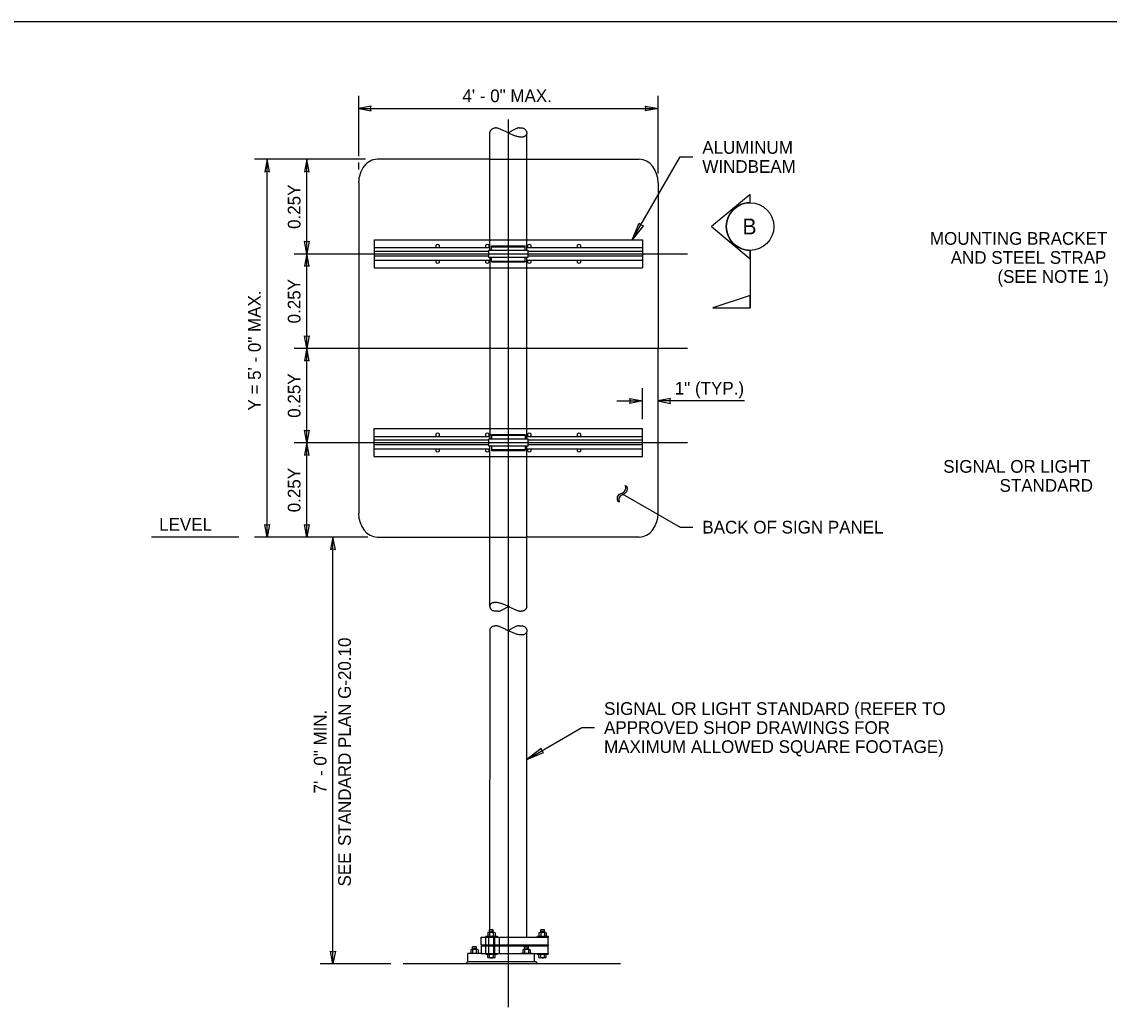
# Model space of a CAD drawing. Extents: x 99862 to 104211, y 98939 to 105076.
# Drawn here: x 101066 to 102436, y 103829 to 105076 of the extents above; entities that cross this region are included whole.
import ezdxf

# ---------------------------------------------------------------- set-up
doc = ezdxf.new("R2010")
doc.units = 0
for name, color, linetype in [('Level 1', 7, 'Continuous'), ('Level 15', 7, 'Continuous'), ('Level 18', 7, 'Continuous'), ('Level 19', 7, 'Continuous'), ('Level 2', 7, 'Continuous'), ('Level 20', 7, 'Continuous'), ('Level 3', 7, 'Continuous'), ('Level 6', 7, 'Continuous'), ('Level 7', 7, 'Continuous')]:
    doc.layers.add(name, color=color, linetype=linetype)

msp = doc.modelspace()

# ---------------------------------------------------------------- linework, layer by layer
at = {"layer": 'Level 1'}
for p, q in [((101656.2, 104902.1), (101514.3, 104902.1)), ((101656.2, 104902.1), (101702.5, 104902.1)), ((101702.5, 104902.1), (101844.4, 104902.1)), ((101490.8, 104872.3), (101490.8, 104455.6)), ((101868, 104872.3), (101867.9, 104455.6)), ((101868, 104872.3), (101868, 104872.3)), ((101867.9, 104455.6), (101867.9, 104455.6)), ((101514.3, 104425.8), (101656.2, 104425.8)), ((101656.2, 104425.8), (101702.5, 104425.8)), ((101844.4, 104425.8), (101702.5, 104425.8)), ((101844.4, 104425.8), (101844.4, 104425.8))]:
    msp.add_line(p, q, dxfattribs=at)
msp.add_lwpolyline([(99862, 102999.5), (103151, 102999.5), (103151, 105075.5), (99862, 105075.5)], close=True, dxfattribs=at)
for centre, major_axis, start_param, end_param in [((101514.3, 104872.3), (0, 29.8), 6.28312, 7.853976), ((101844.4, 104872.3), (0, -29.8), 1.570785, 3.141503), ((101514.3, 104455.6), (0, -29.8), 4.712329, 6.283073), ((101844.4, 104455.6), (0, -29.8), 0, 1.570789)]:
    msp.add_ellipse(centre, major_axis=major_axis, ratio=0.792, start_param=start_param, end_param=end_param, dxfattribs=at)
at = {"layer": 'Level 15'}
for p, q in [((101490.8, 104906.1), (101490.8, 104982.1)), ((101868, 104884.3), (101868, 104982.1)), ((101490.8, 104966.1), (101868, 104966.1)), ((101679.4, 103833.2), (101679.4, 104952.4)), ((101499.3, 104902.1), (101359.5, 104902.1)), ((101375.5, 104425.8), (101375.5, 104902.1)), ((101425.5, 104783), (101425.5, 104902.1)), ((101835.5, 104800.5), (101895.8, 104905)), ((101895.8, 104905), (101911.8, 104905)), ((101490.8, 104889.1), (101490.8, 104898.1)), ((101409.5, 104783), (101905.3, 104783)), ((101425.5, 104663.9), (101425.5, 104783)), ((101409.5, 104663.9), (101905.3, 104664)), ((101425.5, 104544.9), (101425.5, 104663.9)), ((101848.2, 104574.6), (101848.2, 104613.5)), ((101816.2, 104597.5), (101848.2, 104597.5)), ((101977.1, 104597.5), (101867.9, 104597.5)), ((101409.5, 104544.9), (101905.3, 104544.9)), ((101425.5, 104425.8), (101425.5, 104544.9)), ((101827.2, 104488.6), (101826.6, 104491)), ((101826.6, 104491), (101828.3, 104489.8)), ((101828.3, 104489.8), (101829, 104487.9)), ((101816.7, 104474.8), (101817, 104476.4)), ((101817, 104476.4), (101817.7, 104477.9)), ((101817.7, 104477.9), (101819.4, 104479.7)), ((101819.3, 104476.3), (101818.7, 104475)), ((101820.3, 104477.4), (101819.3, 104476.3)), ((101819.4, 104479.7), (101823, 104481.7)), ((101822.4, 104478.7), (101820.3, 104477.4)), ((101826.2, 104480.9), (101822.4, 104478.7)), ((101822.9, 104480.3), (101895.8, 104438.2)), ((101823, 104481.7), (101825.1, 104483)), ((101825.1, 104483), (101826.5, 104484.4)), ((101828.1, 104482.9), (101826.2, 104480.9)), ((101826.5, 104484.4), (101827.1, 104485.6)), ((101827.1, 104485.6), (101827.3, 104486.9)), ((101827.3, 104486.9), (101827.2, 104488.6)), ((101828.8, 104484.5), (101828.1, 104482.9)), ((101829.2, 104486.2), (101828.8, 104484.5)), ((101829, 104487.9), (101829.2, 104486.2)), ((101816.8, 104473), (101816.7, 104474.8)), ((101817.5, 104470.9), (101816.8, 104473)), ((101819.2, 104469.8), (101817.5, 104470.9)), ((101818.7, 104475), (101818.5, 104473.4)), ((101818.5, 104473.4), (101819.2, 104469.8)), ((101895.8, 104438.2), (101911.8, 104438.2)), ((101339.7, 104425.8), (101229.7, 104425.8)), ((101502.3, 104425.8), (101359.5, 104425.8)), ((101458.3, 103887.9), (101458.3, 104425.8)), ((101702.5, 104145.4), (101772, 104185.6)), ((101772, 104185.6), (101788, 104185.6)), ((101531.4, 103887.9), (101442.3, 103887.9))]:
    msp.add_line(p, q, dxfattribs=at)
for points in [[(101490.8, 104966.1), (101506.5, 104963), (101505.8, 104966.1), (101506.5, 104969.2)], [(101868, 104966.1), (101852.2, 104963), (101853, 104966.1), (101852.2, 104969.2)], [(101375.5, 104902.1), (101372.4, 104886.4), (101375.5, 104887.1), (101378.6, 104886.4)], [(101425.5, 104902.1), (101422.4, 104886.3), (101425.5, 104887.1), (101428.6, 104886.3)], [(101835.5, 104800.5), (101844.3, 104821.7), (101846.4, 104819.3), (101849.5, 104818.8)], [(101425.5, 104783), (101422.4, 104798.7), (101425.5, 104798), (101428.6, 104798.7)], [(101425.5, 104783), (101422.4, 104767.3), (101425.5, 104768), (101428.6, 104767.3)], [(101425.5, 104663.9), (101422.4, 104679.7), (101425.5, 104678.9), (101428.6, 104679.7)], [(101425.5, 104663.9), (101422.4, 104648.2), (101425.5, 104648.9), (101428.6, 104648.2)], [(101848.2, 104597.5), (101832.4, 104594.4), (101833.2, 104597.5), (101832.4, 104600.6)], [(101867.9, 104597.5), (101883.7, 104594.4), (101882.9, 104597.5), (101883.7, 104600.6)], [(101425.5, 104544.9), (101422.4, 104560.6), (101425.5, 104559.9), (101428.6, 104560.6)], [(101425.5, 104544.9), (101422.4, 104529.2), (101425.5, 104529.9), (101428.6, 104529.2)], [(101375.5, 104425.8), (101372.4, 104441.6), (101375.5, 104440.8), (101378.6, 104441.6)], [(101425.5, 104425.8), (101422.4, 104441.6), (101425.5, 104440.8), (101428.6, 104441.6)], [(101458.3, 104425.8), (101455.2, 104410.1), (101458.3, 104410.8), (101461.4, 104410.1)], [(101702.5, 104145.4), (101723.8, 104154.3), (101721.4, 104156.3), (101720.8, 104159.4)], [(101458.3, 103887.9), (101455.2, 103903.6), (101458.3, 103902.9), (101461.4, 103903.6)]]:
    msp.add_lwpolyline(points, close=True, dxfattribs=at)
at = {"layer": 'Level 18'}
for p, q in [((101661.5, 103927.2), (101654.5, 103927.2)), ((101655.5, 103927.2), (101655.5, 103930.5)), ((101660.4, 103930.5), (101655.5, 103930.5)), ((101656.8, 103928.9), (101659.3, 103928.9)), ((101660.4, 103927.2), (101660.4, 103930.5)), ((101726.1, 103927.2), (101719.1, 103927.2)), ((101720.1, 103927.2), (101720.1, 103930.5)), ((101725, 103930.5), (101720.1, 103930.5)), ((101721.3, 103928.9), (101723.9, 103928.9)), ((101725, 103927.2), (101725, 103930.5)), ((101645, 103911.7), (101645, 103921.5)), ((101645, 103921.5), (101729.5, 103921.5)), ((101651.1, 103922.7), (101665.1, 103922.7)), ((101651.1, 103922.7), (101651.1, 103921.5)), ((101651.1, 103911.7), (101651.1, 103921.5)), ((101653.4, 103926.8), (101653.4, 103922.7)), ((101654.8, 103911.7), (101654.8, 103921.5)), ((101655.6, 103926.9), (101655.6, 103922.7)), ((101660.3, 103926.9), (101660.3, 103922.7)), ((101661, 103911.7), (101661, 103921.5)), ((101662.2, 103911.7), (101662.2, 103921.5)), ((101662.6, 103926.8), (101662.6, 103922.7)), ((101665.1, 103922.7), (101665.1, 103921.5)), ((101668.4, 103911.7), (101668.4, 103921.5)), ((101715.5, 103922.7), (101729.5, 103922.7)), ((101715.5, 103922.7), (101715.5, 103921.5)), ((101717.9, 103926.8), (101717.9, 103922.7)), ((101720.2, 103926.9), (101720.2, 103922.7)), ((101724.9, 103926.9), (101724.9, 103922.7)), ((101727.2, 103926.8), (101727.2, 103922.7)), ((101729.5, 103922.7), (101729.5, 103921.5)), ((101729.5, 103911.7), (101729.5, 103921.5)), ((101628.2, 103890.7), (101628.2, 103900.6)), ((101645, 103900.6), (101628.2, 103900.6)), ((101629.4, 103901.4), (101643.7, 103901.4)), ((101629.4, 103901.4), (101629.4, 103900.6)), ((101632, 103905.5), (101632, 103901.4)), ((101640.1, 103905.9), (101633.2, 103905.9)), ((101634.2, 103905.9), (101634.2, 103909.2)), ((101639.1, 103909.2), (101634.2, 103909.2)), ((101634.3, 103905.5), (101634.3, 103901.4)), ((101635.4, 103907.6), (101638, 103907.6)), ((101639, 103905.6), (101639, 103901.4)), ((101639.1, 103905.9), (101639.1, 103909.2)), ((101641.3, 103905.5), (101641.3, 103901.4)), ((101643.7, 103901.4), (101643.7, 103900.6)), ((101645, 103911.7), (101729.5, 103911.7)), ((101645, 103910.4), (101729.5, 103910.4)), ((101645, 103910.4), (101645, 103900.6)), ((101645, 103900.6), (101729.5, 103900.6)), ((101651.1, 103911.7), (101651.1, 103910.4)), ((101651.1, 103900.6), (101651.1, 103910.4)), ((101651.1, 103900.6), (101651.1, 103899.8)), ((101651.1, 103899.8), (101665.1, 103899.8)), ((101653.6, 103895.7), (101653.6, 103899.8)), ((101654.8, 103900.6), (101654.8, 103910.4)), ((101655.8, 103895.6), (101655.8, 103899.8)), ((101660.5, 103895.6), (101660.5, 103899.8)), ((101661, 103900.6), (101661, 103910.4)), ((101662.2, 103900.6), (101662.2, 103910.4)), ((101662.8, 103895.7), (101662.8, 103899.8)), ((101665.1, 103911.7), (101665.1, 103910.4)), ((101665.1, 103900.6), (101665.1, 103899.8)), ((101668.4, 103900.6), (101668.4, 103910.4)), ((101695, 103901.4), (101709.4, 103901.4)), ((101695, 103901.4), (101695, 103900.6)), ((101697.6, 103905.5), (101697.6, 103901.4)), ((101705.8, 103905.9), (101698.8, 103905.9)), ((101699.8, 103905.9), (101699.8, 103909.2)), ((101704.7, 103909.2), (101699.8, 103909.2)), ((101699.9, 103905.5), (101699.9, 103901.4)), ((101701, 103907.6), (101703.6, 103907.6)), ((101704.6, 103905.6), (101704.6, 103901.4)), ((101704.7, 103905.9), (101704.7, 103909.2)), ((101706.9, 103905.5), (101706.9, 103901.4)), ((101709.4, 103901.4), (101709.4, 103900.6)), ((101712.2, 103890.7), (101712.2, 103900.6)), ((101715.5, 103911.7), (101715.5, 103910.4)), ((101715.5, 103900.6), (101715.5, 103899.8)), ((101715.5, 103899.8), (101729.5, 103899.8)), ((101717.9, 103895.7), (101717.9, 103899.8)), ((101720.2, 103895.6), (101720.2, 103899.8)), ((101724.9, 103895.6), (101724.9, 103899.8)), ((101727.2, 103895.7), (101727.2, 103899.8)), ((101729.5, 103911.7), (101729.5, 103910.4)), ((101729.5, 103900.6), (101729.5, 103910.4)), ((101729.5, 103900.6), (101729.5, 103899.8)), ((101820.7, 103887.9), (101546.9, 103887.9)), ((101625.3, 103887.9), (101628.2, 103890.7)), ((101628.2, 103890.7), (101713.9, 103890.7)), ((101661.7, 103895.3), (101654.7, 103895.3)), ((101716.7, 103887.9), (101713.9, 103890.7)), ((101726.1, 103895.3), (101719.1, 103895.3))]:
    msp.add_line(p, q, dxfattribs=at)
for centre, radius, start, end in [((101654.5, 103925.4), 1.81, 52.3034, 130.9523), ((101658, 103919.5), 7.78, 72.912, 107.9146), ((101661.4, 103925.3), 1.95, 52.6587, 124.5047), ((101719.1, 103925.4), 1.81, 52.3034, 130.9523), ((101722.6, 103919.5), 7.78, 72.912, 107.9146), ((101726, 103925.3), 1.95, 52.6587, 124.5047), ((101633.2, 103904.1), 1.81, 52.3034, 130.9523), ((101636.7, 103898.1), 7.78, 72.912, 107.9146), ((101640.1, 103904), 1.95, 52.6587, 124.5047), ((101698.8, 103904.1), 1.81, 52.3034, 130.9523), ((101702.3, 103898.1), 7.78, 72.912, 107.9146), ((101705.7, 103904), 1.95, 52.6587, 124.5047), ((101654.7, 103897.1), 1.81, 229.0477, 307.6966), ((101658.2, 103903), 7.78, 252.0854, 287.088), ((101661.6, 103897.2), 1.95, 235.4953, 307.3413), ((101719.1, 103897.1), 1.81, 229.0477, 307.6966), ((101722.6, 103903), 7.78, 252.0854, 287.088), ((101726, 103897.2), 1.95, 235.4953, 307.3413)]:
    msp.add_arc(centre, radius, start, end, dxfattribs=at)
at = {"layer": 'Level 19'}
for p, q in [((101656.2, 104787.6), (101656.2, 104935.8)), ((101702.5, 104787.6), (101702.5, 104934.3)), ((101656.2, 104778.2), (101656.2, 104549.7)), ((101702.5, 104549.7), (101702.5, 104778.2)), ((101656.2, 104338.7), (101656.2, 104540.3)), ((101702.5, 104338.4), (101702.5, 104540.3)), ((101656.1, 103930.5), (101656.3, 104309.7)), ((101702.5, 103921.5), (101702.5, 104306.4))]:
    msp.add_line(p, q, dxfattribs=at)
for points in [[(101692.8, 104941.6), (101695.8, 104941.6)], [(101666, 104332.2), (101663.1, 104332.2)], [(101692.8, 104314), (101695.8, 104314)]]:
    msp.add_lwpolyline(points, dxfattribs=at)
for points in [[(101656.2, 104935.3), (101656.2, 104935.4), (101656.2, 104935.9), (101656.3, 104936.6), (101656.6, 104937.5), (101657.1, 104938.5), (101657.8, 104939.3), (101658.6, 104940.1), (101659.8, 104940.9), (101661.2, 104941.4), (101662.3, 104941.6), (101663, 104941.6)], [(101695.8, 104941.6), (101696.4, 104941.6), (101697.6, 104941.4), (101699, 104940.9), (101700.1, 104940.1), (101701, 104939.3), (101701.6, 104938.4), (101702.1, 104937.6), (101702.4, 104936.6), (101702.5, 104935.7), (101702.6, 104934.5), (101702.4, 104933.9), (101702, 104933), (101701.5, 104932.2), (101700.7, 104931.4), (101699.7, 104930.8), (101698.4, 104930.3), (101696.8, 104930), (101694.9, 104930), (101692.8, 104930.3), (101690.7, 104930.7), (101688.5, 104931.4), (101686.5, 104932.2), (101684.4, 104933), (101682.4, 104933.8), (101680.5, 104934.8), (101678.6, 104935.7), (101676.7, 104936.6), (101674.8, 104937.5), (101672.9, 104938.4), (101670.9, 104939.3), (101669, 104940.1), (101667, 104940.9), (101665, 104941.4), (101663.7, 104941.6), (101663.1, 104941.6)], [(101692.8, 104941.6), (101692.2, 104941.6), (101691.1, 104941.4), (101689.5, 104940.8), (101687.9, 104940.1), (101686.3, 104939.3), (101684.7, 104938.4), (101683.2, 104937.6), (101681.7, 104936.6), (101680.4, 104935.9), (101679.6, 104935.4), (101679.4, 104935.3)], [(101663.1, 104332.2), (101662.4, 104332.2), (101661.3, 104332.3), (101659.8, 104332.9), (101658.7, 104333.6), (101657.9, 104334.4), (101657.2, 104335.3), (101656.7, 104336.2), (101656.4, 104337.1), (101656.3, 104338.1), (101656.2, 104338.7), (101656.5, 104339.9), (101656.8, 104340.7), (101657.3, 104341.6), (101658.1, 104342.3), (101659.1, 104343), (101660.5, 104343.5), (101662.1, 104343.7), (101664, 104343.7), (101666, 104343.5), (101668.2, 104343), (101670.3, 104342.3), (101672.4, 104341.6), (101674.4, 104340.8), (101676.4, 104339.9), (101678.3, 104339), (101680.2, 104338.1), (101682.1, 104337.1), (101684, 104336.2), (101685.9, 104335.3), (101687.9, 104334.4), (101689.8, 104333.6), (101691.8, 104332.9), (101693.8, 104332.3), (101695.1, 104332.2), (101695.7, 104332.2)], [(101666, 104332.2), (101666.6, 104332.2), (101667.7, 104332.3), (101669.3, 104332.9), (101670.9, 104333.6), (101672.5, 104334.4), (101674.1, 104335.3), (101675.6, 104336.2), (101677.2, 104337.1), (101678.4, 104337.9), (101679.2, 104338.3), (101679.4, 104338.4)], [(101702.5, 104338.4), (101702.5, 104338.3), (101702.5, 104337.9), (101702.4, 104337.1), (101702.1, 104336.2), (101701.6, 104335.3), (101701, 104334.4), (101700.1, 104333.6), (101699, 104332.9), (101697.6, 104332.3), (101696.4, 104332.2), (101695.7, 104332.2)], [(101656.3, 104309.7), (101656.4, 104309.8), (101656.5, 104310.2), (101656.9, 104310.9), (101657.5, 104311.8), (101658.4, 104312.6), (101659.6, 104313.3), (101661, 104313.9), (101662.1, 104314), (101662.8, 104314)], [(101695.8, 104314), (101696.5, 104314), (101697.6, 104313.9), (101699.1, 104313.3), (101700.2, 104312.6), (101701.1, 104311.8), (101701.7, 104310.9), (101702.2, 104310), (101702.5, 104309), (101702.7, 104308.1), (101702.7, 104307.2), (101702.5, 104306.3), (101702.2, 104305.4), (101701.6, 104304.6), (101700.8, 104303.8), (101699.8, 104303.1), (101698.5, 104302.6), (101696.8, 104302.4), (101694.9, 104302.4), (101692.8, 104302.6), (101690.7, 104303.1), (101688.5, 104303.8), (101686.4, 104304.5), (101684.4, 104305.4), (101682.4, 104306.2), (101680.4, 104307.2), (101678.5, 104308.1), (101676.5, 104309), (101674.7, 104310), (101672.7, 104310.9), (101670.8, 104311.8), (101668.8, 104312.6), (101666.8, 104313.3), (101664.8, 104313.9), (101663.5, 104314), (101662.8, 104314)], [(101692.8, 104314), (101692.3, 104314), (101691.2, 104313.9), (101689.5, 104313.3), (101687.9, 104312.6), (101686.3, 104311.8), (101684.7, 104310.9), (101683.1, 104310), (101681.6, 104309), (101680.3, 104308.3), (101679.5, 104307.8), (101679.3, 104307.7)]]:
    msp.add_open_spline(points, degree=3, dxfattribs=at)
at = {"layer": 'Level 2'}
for p, q in [((101510.5, 104800.5), (101510.5, 104765.3)), ((101510.5, 104800.5), (101656.2, 104800.5)), ((101510.5, 104790.7), (101656.2, 104790.7)), ((101656.2, 104800.5), (101702.5, 104800.5)), ((101702.5, 104800.5), (101848.2, 104800.5)), ((101702.5, 104790.7), (101848.2, 104790.7)), ((101848.2, 104800.5), (101848.2, 104765.3)), ((101654.7, 104786), (101510.5, 104786)), ((101654.7, 104779.8), (101510.5, 104779.8)), ((101848.2, 104786), (101704.1, 104786)), ((101848.2, 104779.8), (101704.1, 104779.8)), ((101510.5, 104775.1), (101656.2, 104775.1)), ((101510.5, 104765.3), (101656.2, 104765.3)), ((101656.2, 104765.3), (101702.5, 104765.3)), ((101702.5, 104775.1), (101848.2, 104775.1)), ((101702.5, 104765.3), (101848.2, 104765.3)), ((101510.5, 104527.4), (101510.5, 104562.6)), ((101510.5, 104562.6), (101656.2, 104562.6)), ((101656.2, 104562.6), (101702.5, 104562.6)), ((101702.5, 104562.6), (101848.2, 104562.6)), ((101848.2, 104527.4), (101848.2, 104562.6)), ((101510.5, 104552.8), (101656.2, 104552.8)), ((101654.7, 104548.1), (101510.5, 104548.1)), ((101702.5, 104552.8), (101848.2, 104552.8)), ((101848.2, 104548.1), (101704.1, 104548.1)), ((101654.7, 104541.9), (101510.5, 104541.9)), ((101510.5, 104537.2), (101656.2, 104537.2)), ((101702.5, 104537.2), (101848.2, 104537.2)), ((101848.2, 104541.9), (101704.1, 104541.9)), ((101510.5, 104527.4), (101656.2, 104527.4)), ((101656.2, 104527.4), (101702.5, 104527.4)), ((101702.5, 104527.4), (101848.2, 104527.4))]:
    msp.add_line(p, q, dxfattribs=at)
at = {"layer": 'Level 20'}
for p, q in [((101983.9, 104857.9), (101935.4, 104817.3)), ((101983.9, 104847.3), (101983.9, 104857.9)), ((101935.4, 104817.3), (101983.9, 104776.7)), ((101983.9, 104776.7), (101983.9, 104787.3)), ((101983.9, 104787.3), (101983.9, 104714.9))]:
    msp.add_line(p, q, dxfattribs=at)
msp.add_lwpolyline([(101983.9, 104730.5), (101937, 104714.9), (101983.9, 104714.9)], close=True, dxfattribs=at)
msp.add_circle((101983.9, 104817.3), 30, dxfattribs=at)
msp.add_arc((101983.9, 104817.3), 30, 89.9978, 270.0022, dxfattribs=at)
at = {"layer": 'Level 3'}
for p, q in [((101695.7, 104930), (101695.7, 104930)), ((101658.3, 104791.8), (101658.3, 104792.9)), ((101658.3, 104792.9), (101700.5, 104792.9)), ((101658.3, 104791.8), (101700.5, 104791.8)), ((101658.3, 104787.6), (101658.3, 104791.8)), ((101700.5, 104791.8), (101700.5, 104792.9)), ((101700.5, 104787.6), (101700.5, 104791.8)), ((101658.3, 104773.7), (101658.3, 104778.2)), ((101700.5, 104773.7), (101700.5, 104778.2)), ((101658.3, 104773.7), (101658.3, 104772.6)), ((101658.3, 104773.7), (101700.5, 104773.7)), ((101658.3, 104772.6), (101700.5, 104772.6)), ((101700.5, 104773.7), (101700.5, 104772.6)), ((101658.3, 104554.2), (101658.3, 104555.3)), ((101658.3, 104555.3), (101700.5, 104555.3)), ((101658.3, 104554.2), (101700.5, 104554.2)), ((101658.3, 104554.2), (101658.3, 104549.7)), ((101700.5, 104554.2), (101700.5, 104555.3)), ((101700.5, 104554.2), (101700.5, 104549.7)), ((101658.3, 104540.3), (101658.3, 104536.1)), ((101658.3, 104536.1), (101658.3, 104535)), ((101658.3, 104536.1), (101700.5, 104536.1)), ((101658.3, 104535), (101700.5, 104535)), ((101679.4, 104536.1), (101679.4, 104535)), ((101700.5, 104540.3), (101700.5, 104536.1)), ((101700.5, 104536.1), (101700.5, 104535)), ((101695.8, 104302.4), (101695.8, 104302.4))]:
    msp.add_line(p, q, dxfattribs=at)
at = {"layer": 'Level 6'}
for centre, start, end in [((101590.4, 104792.5), 90, 230.0555), ((101590.4, 104792.5), 309.9445, 90), ((101652.9, 104792.5), 90, 230.0555), ((101652.9, 104792.5), 309.9445, 90), ((101705.8, 104792.5), 90, 230.0555), ((101705.8, 104792.5), 309.9445, 90), ((101768.3, 104792.5), 90, 230.0555), ((101768.3, 104792.5), 309.9445, 90), ((101590.4, 104773.3), 129.9445, 270), ((101590.4, 104773.3), 270, 50.0555), ((101652.9, 104773.3), 129.9445, 270), ((101652.9, 104773.3), 270, 50.0555), ((101705.8, 104773.3), 129.9445, 270), ((101705.8, 104773.3), 270, 50.0555), ((101768.3, 104773.3), 129.9445, 270), ((101768.3, 104773.3), 270, 50.0555), ((101590.4, 104554.6), 90, 230.0555), ((101590.4, 104554.6), 309.9445, 90), ((101652.9, 104554.6), 90, 230.0555), ((101652.9, 104554.6), 309.9445, 90), ((101705.8, 104554.6), 90, 230.0555), ((101705.8, 104554.6), 309.9445, 90), ((101768.3, 104554.6), 90, 230.0555), ((101768.3, 104554.6), 309.9445, 90), ((101590.4, 104535.4), 129.9445, 270), ((101590.4, 104535.4), 270, 50.0555), ((101652.9, 104535.4), 129.9445, 270), ((101652.9, 104535.4), 270, 50.0555), ((101705.8, 104535.4), 129.9445, 270), ((101705.8, 104535.4), 270, 50.0555), ((101768.3, 104535.4), 129.9445, 270), ((101768.3, 104535.4), 270, 50.0555)]:
    msp.add_arc(centre, 2.34, start, end, dxfattribs=at)
at = {"layer": 'Level 7'}
for p, q in [((101654.7, 104778.2), (101654.7, 104787.6)), ((101654.7, 104787.6), (101704.1, 104787.6)), ((101704.1, 104778.2), (101654.7, 104778.2)), ((101704.1, 104787.6), (101704.1, 104778.2)), ((101654.8, 104540.3), (101654.8, 104549.7)), ((101654.8, 104549.7), (101703.9, 104549.7)), ((101703.9, 104549.7), (101703.9, 104540.3)), ((101703.9, 104540.3), (101654.8, 104540.3))]:
    msp.add_line(p, q, dxfattribs=at)

# ---------------------------------------------------------------- texts
at = {"layer": 'Level 20'}
for s, height, p in [('4\' - 0" MAX.', 16, (101621.5, 104974.1)), ('B', 20, (101974.3, 104807.4)), ('1" (TYP.)', 16, (101889.1, 104605.5)), ('SIGNAL OR LIGHT', 16, (102227.3, 104506.9)), ('STANDARD', 16, (102298.3, 104482.9)), ('LEVEL', 16, (101239.4, 104433.8)), ('SIGNAL OR LIGHT STANDARD (REFER TO ', 16, (101800, 104201.6)), ('APPROVED SHOP DRAWINGS FOR ', 16, (101800, 104177.6)), ('MAXIMUM ALLOWED SQUARE FOOTAGE)', 16, (101800, 104153.6))]:
    msp.add_text(s, height=height, dxfattribs=at).set_placement(p)
for s, rotation, p in [('ALUMINUM', 360, (101923.8, 104909)), ('WINDBEAM', 360, (101923.8, 104885)), ('0.25Y', 90, (101417.5, 104814.3)), ('MOUNTING BRACKET', 360, (102210.5, 104794.3)), ('AND STEEL STRAP', 360, (102236.7, 104770.3)), ('(SEE NOTE 1)', 360, (102295.6, 104746.3)), ('0.25Y', 90, (101417.5, 104695.2)), ('Y = 5\' - 0" MAX.', 90, (101367.5, 104585.3)), ('0.25Y', 90, (101417.5, 104576.2)), ('0.25Y', 90, (101417.5, 104457.1)), ('BACK OF SIGN PANEL', 360, (101923.8, 104430.3)), ('STANDARD PLAN G-20.10', 90, (101481, 104036.3)), ('7\' - 0" MIN.', 90, (101450.3, 104102.6)), ('SEE ', 90, (101481, 103985.3))]:
    msp.add_text(s, height=16, rotation=rotation, dxfattribs=at).set_placement(p)

doc.saveas('drawing.dxf')
